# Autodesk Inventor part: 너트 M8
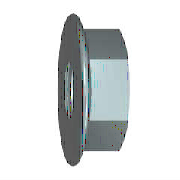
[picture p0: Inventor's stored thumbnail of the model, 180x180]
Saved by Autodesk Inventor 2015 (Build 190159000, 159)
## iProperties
Created: 2015-09
Part Number: 너트 M8
Material: 스테인리스강
Description: 플랜지붙이 6각 너트 - 일반 스레드
Document SubType Name: Modeling
Standard: ISO 4161
Designer: mduedu
Standard Revision: 2판 1999-03-15
Standards Organization: ISO
Language: ko-KR
Size Designation: M8
Categories: <MemberInstance><Categories><Category DisplayName="조임쇠" InternalName="e4da775c-781d-43d5-af7c-5136215cf5a6" Mnemonic="FSTN"><Category DisplayName="너트" InternalN
Density: 8.08 g/cm^3
Appearance: 기본값
Author: mduedu
IsCustomPart: 1
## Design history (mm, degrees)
sketch "스케치1"
  geometry: L1 (-1.844, 0)-(9.641, 0) reference; L2 (3.107, 6.5)-(2.288, 8.257); L3 (3.107, 6.5)-(8, 6.5); L4 (8, 6.5)-(8, 0); L5 (3.107, 6.5)-(3.107, 0); L6 (0, -1.835)-(0, 11.01) reference; A1 r 1.2 centre (1.2, 7.75) between (2.288, 8.257) and (0, 7.75); 1 further point
  constraints: 8 end point, 3 point on line, 2 perpendicular, 2 point on circle, 2 tangent, 1 centre point, 1 parallel
  dimensions: "d2" = 13 diameter of L3 L1 (= SW); "d4" = 17.9 dimension on A1 L1 (= LADI); "d5" = 1.2 radius of A1 (= PHH); "d15" = 8 distance between parallel lines of L4 L6 (= KOH); "d16" = 25 deg angle of L6 L2 (= KEWI)
revolve "링" sketch "스케치1" stored, may be unused: angle "d8" = 90 deg
sketch "스케치2"
  geometry: L1 (-6.5, -3.753)-(-6.5, 3.753); L2 (-6.5, 3.753)-(0, 7.506); L3 (0, 7.506)-(6.5, 3.753); L4 (6.5, 3.753)-(6.5, -3.753); L5 (6.5, -3.753)-(0, -7.506); L6 (0, -7.506)-(-6.5, -3.753); C1 r 4.9 at (0, 0); C2 r 7.75 at (0, 0) reference; 1 further point
  constraints: 12 end point, 1 centre point, 1 coincident, 1 vertical, 11 other
  dimensions: "d6" = 15.01111 distance of L5.end L2.end (= 1.1547 x SW)
extrude "본체" join sketch "스케치2" distance "d7" = 8 (= KOH); taper "d9" = 0 deg
sketch "스케치3"
  geometry: L1 (2.638, 7.506)-(8, 7.506) reference; L2 (8, 3.753)-(8, 7.506) reference; L3 (0, -7.75)-(0, 7.75) reference; L4 (-1.6, 0)-(9.6, 0) reference; L5 (7.419, 7.506)-(8, 6.5)
  constraints: 2 end point, 2 point on line
  dimensions: "d10" = 30 deg angle of L2 L5 (= ANG1); "d11" = 13 diameter of L5.end L4 (= SW0)
revolve "모따기1" sketch "스케치3" stored, may be unused: angle "d24" = 90 deg
sketch "스케치4"
  geometry: C1 r 7.75 at (0, 0) reference; 1 further point
  constraints: 1 coincident
hole "스레드" sketch "스케치4" at (0, 0) diameter "d25" = 6.647; stored, may be unused: countersink angle "d29" = 82 deg, drill point angle "d31" = 118 deg; dims "d26" = 6, "d27" = 4, "d28" = 2, "d30" = 8
workaxis "Work Axis1"
workplane "Work Plane1"
body "Solid1"
chamfer "모따기2" distance "d12" = 0.67658 (= -0.5 x GD1 + 0.5 x NND); stored, may be unused: angle "d13" = 30 deg, second distance "d46" = 0.67658 (= -0.5 x GD1 + 0.5 x NND)
chamfer "모따기3" distance "d51" = 0.67658 (= -0.5 x GD1 + 0.5 x NND); stored, may be unused: second distance "d52" = 2, angle "d53" = 45 deg
other parameters: "ANG1" = 30 deg [user parameter; used in 1 equation term], "KEWI" = 25 deg [user parameter; used in 1 equation term], "NND" = 8 [user parameter; used in 4 equation terms], "LADI" = 17.9 [user parameter; used in 2 equation terms], "SW" = 13 [user parameter; used in 3 equation terms], "PHH" = 1.2 [user parameter; used in 3 equation terms], "KOH" = 8 (= NND) [user parameter; used in 2 equation terms], "SW0" = 13 [user parameter; used in 1 equation term], "GD1" = 6.64684 (computed from THREADDIA, PTC, TOA) [user parameter; used in 3 equation terms], "d1" = 17.9 (= LADI), "d3" = 1.2 (= PHH), "d45" = 0, "d47" = 0, "d49" = 0, "d54" = 0, "GUL" = 0.67658 (= 0.541266 x PTC) [user parameter], "TPU" = 8 (computed from PTC) [user parameter], "RR" = 1.2 (= PHH) [user parameter], "THREADDIA" = 8 [user parameter; used in 1 equation term], "TOA" = 30 deg [user parameter; used in 1 equation term], "PTC" = 1.25 [user parameter; used in 4 equation terms], "GAL" = 0.67658 (= 0.541266 x PTC) [user parameter], "E0" = 15.015 (= 1.155 x SW) [user parameter]
